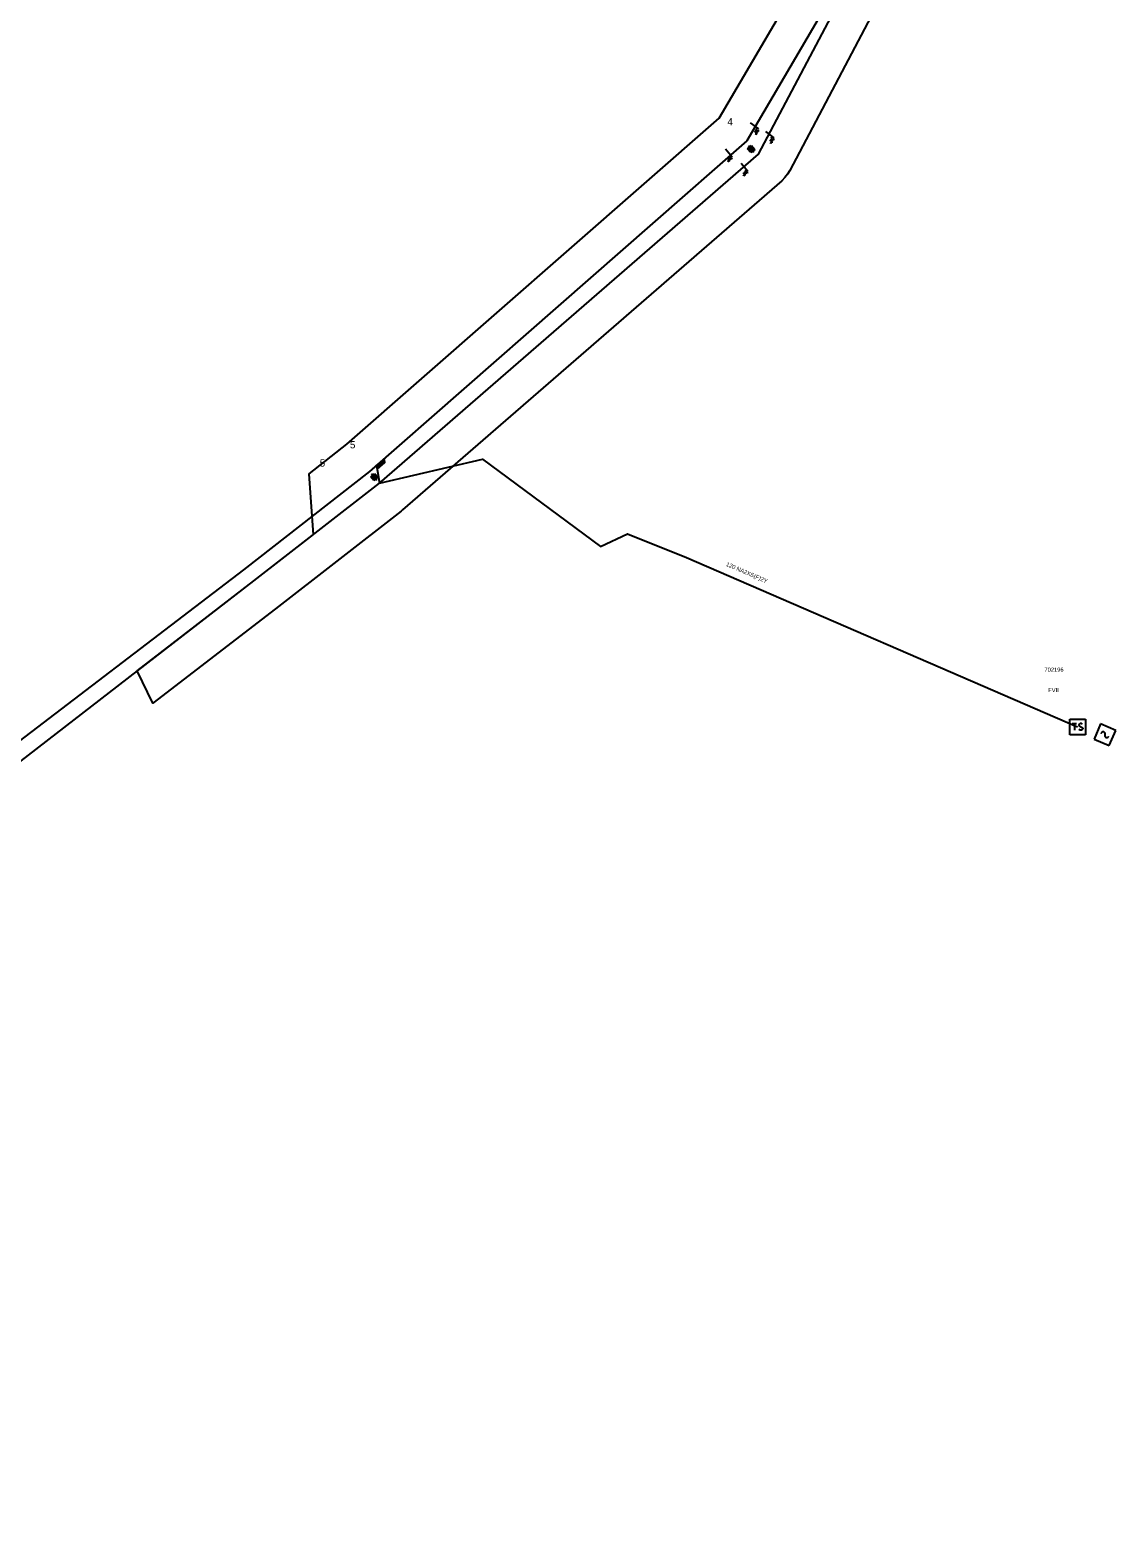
# Model space of a CAD drawing. Extents: x -788491 to -785797, y -1154753 to -1152002.
# Drawn here: x -787842.2 to -787580.7, y -1154362.4 to -1153999.5 of the extents above; entities that cross this region are included whole.
import ezdxf

# ---------------------------------------------------------------- set-up
doc = ezdxf.new("R2010")
doc.units = 0
for name, color, linetype in [('Default', 7, 'Continuous'), ('Vrstva 1', 7, 'Continuous'), ('Vrstva 11', 7, 'Continuous'), ('Vrstva 12', 7, 'Continuous'), ('Vrstva 13', 7, 'Continuous'), ('Vrstva 14', 7, 'Continuous'), ('Vrstva 15', 7, 'Continuous'), ('Vrstva 18', 7, 'Continuous'), ('Vrstva 2', 7, 'Continuous'), ('Vrstva 25', 7, 'Continuous'), ('Vrstva 26', 7, 'Continuous'), ('Vrstva 27', 7, 'Continuous'), ('Vrstva 34', 7, 'Continuous'), ('Vrstva 35', 7, 'Continuous'), ('Vrstva 5', 7, 'Continuous'), ('Vrstva 6', 7, 'Continuous')]:
    doc.layers.add(name, color=color, linetype=linetype)

# ---------------------------------------------------------------- blocks, each defined once
blk = doc.blocks.new('VN840')
at = {"layer": 'Vrstva 15'}
for points in [[(-0.01, 1.41), (-0.01, -1.09)], [(-1.51, -1.24), (-1.51, -1.15)], [(-1.48, -1.35), (-1.51, -1.24)], [(-1.33, -1.42), (-1.48, -1.35)], [(-1.27, -1.42), (-1.33, -1.42)], [(-1.13, -1.35), (-1.27, -1.42)], [(-1.09, -1.24), (-1.13, -1.35)], [(-1.09, -0.59), (-1.09, -1.24)], [(-0.68, -0.59), (-0.68, -1.42)], [(-0.68, -1.11), (-0.27, -0.59)], [(-0.54, -0.94), (-0.2, -1.42)]]:
    blk.add_lwpolyline(points, dxfattribs=at)
blk = doc.blocks.new('VN740')
at = {"layer": 'Vrstva 1'}
for points in [[(2, 2), (-2, 2)], [(-2, 2), (-2, -2)], [(0, 0), (0, 0.05), (-0.01, 0.1), (-0.02, 0.15), (-0.04, 0.2), (-0.06, 0.24), (-0.09, 0.29), (-0.12, 0.33), (-0.16, 0.36), (-0.2, 0.4), (-0.24, 0.42), (-0.29, 0.45), (-0.34, 0.47), (-0.38, 0.48), (-0.44, 0.49), (-0.49, 0.49), (-0.54, 0.49), (-0.59, 0.48), (-0.64, 0.47), (-0.69, 0.45), (-0.73, 0.43), (-0.77, 0.4), (-0.81, 0.37), (-0.85, 0.33), (-0.88, 0.29), (-0.91, 0.25), (-0.93, 0.2), (-0.95, 0.16), (-0.97, 0.11), (-0.97, 0.06), (-0.98, 0), (-0.98, 0)], [(2, -2), (2, 2)], [(-2, -2), (2, -2)], [(0, 0), (0, -0.05), (0.01, -0.1), (0.02, -0.15), (0.04, -0.2), (0.06, -0.24), (0.09, -0.28), (0.12, -0.32), (0.15, -0.36), (0.19, -0.39), (0.23, -0.42), (0.28, -0.44), (0.32, -0.46), (0.37, -0.48), (0.42, -0.49), (0.47, -0.49), (0.52, -0.49), (0.57, -0.48), (0.62, -0.47), (0.67, -0.45), (0.71, -0.43), (0.75, -0.4), (0.79, -0.37), (0.83, -0.34), (0.86, -0.3), (0.89, -0.26), (0.91, -0.21), (0.93, -0.17), (0.95, -0.12), (0.96, -0.07), (0.96, -0.02), (0.96, -0.02)]]:
    blk.add_lwpolyline(points, dxfattribs=at)
blk = doc.blocks.new('VN640')
at = {"layer": 'Vrstva 6'}
for points in [[(-1.89, 1.89), (1.89, 1.89)], [(-1.89, -1.89), (-1.89, 1.89)], [(-1.26, 0.79), (-0.22, 0.79)], [(-0.73, 0.79), (-0.73, -0.79)], [(1.2, 0.66), (0.94, 0.79), (0.66, 0.79), (0.41, 0.66), (0.28, 0.47), (0.28, 0.41), (0.41, 0.22), (1.13, -0.16), (1.26, -0.32), (1.26, -0.47), (1.13, -0.66), (0.91, -0.79), (0.63, -0.79), (0.5, -0.73), (0.28, -0.6)], [(1.89, 1.89), (1.89, -1.89)], [(1.89, -1.89), (-1.89, -1.89)]]:
    blk.add_lwpolyline(points, dxfattribs=at)
blk = doc.blocks.new('VN001')
at = {"layer": 'Default'}
for p, q in [((2.07, 3.63), (4.49, 3.63)), ((2.1, 3.68), (4.52, 3.68)), ((2.13, 3.73), (2.54, 3.73)), ((1.73, 3.03), (4.14, 3.03)), ((1.76, 3.08), (4.17, 3.08)), ((1.79, 3.13), (4.2, 3.13)), ((1.82, 3.18), (4.23, 3.18)), ((1.85, 3.23), (4.26, 3.23)), ((1.87, 3.28), (4.29, 3.28)), ((1.9, 3.33), (4.32, 3.33)), ((1.93, 3.38), (4.35, 3.38)), ((1.96, 3.43), (4.37, 3.43)), ((1.99, 3.48), (4.4, 3.48)), ((2.02, 3.53), (4.43, 3.53)), ((2.05, 3.58), (4.46, 3.58))]:
    blk.add_line(p, q, dxfattribs=at)
blk.add_lwpolyline([(2.13, 3.73), (0, 0)], dxfattribs=at)
blk.add_lwpolyline([(4.55, 3.73), (2.13, 3.73), (1.7, 2.98), (4.12, 2.99)], close=True, dxfattribs=at)
blk = doc.blocks.new('VN470')
at = {"layer": 'Vrstva 2'}
for points in [[(-1.23, 1.22), (1.23, 1.22)], [(-1.23, -1.23), (-1.23, 1.22)], [(-0.92, 0.9), (0.92, 0.9)], [(-0.92, -0.95), (-0.92, 0.9)], [(-0.61, 0.61), (0.61, 0.61)], [(-0.61, -0.62), (-0.61, 0.61)], [(-0.31, -0.27), (-0.31, 0.34)], [(-0.31, 0.34), (0.31, 0.34)], [(0, 1.22), (0, 1.97)], [(0.31, 0.34), (0.31, -0.27)], [(0.61, 0.61), (0.61, -0.62)], [(0.92, 0.9), (0.92, -0.95)], [(1.23, 1.22), (1.23, -1.23)], [(1.23, -1.23), (-1.23, -1.23)], [(0.92, -0.95), (-0.92, -0.95)], [(0.61, -0.62), (-0.61, -0.62)], [(0.31, -0.27), (-0.31, -0.27)], [(0, -1.23), (0, -1.98)]]:
    blk.add_lwpolyline(points, dxfattribs=at)

msp = doc.modelspace()

# ---------------------------------------------------------------- linework, layer by layer
at = {"layer": 'Vrstva 1'}
for points in [[(-787758.04, -1154108.54), (-787666.77, -1154029.34), (-787645.62, -1153989.29), (-787637.12, -1153973.58), (-787604.57, -1153915.79), (-787595.6, -1153858.98)], [(-787607.03, -1153915.49), (-787637.43, -1153970.03), (-787646.17, -1153986.09), (-787669.6, -1154026.19), (-787760.49, -1154105.76), (-787790.77, -1154129.38), (-787853.74, -1154177.36), (-787944.45, -1154251.81), (-787941.69, -1154348.3), (-787939.33, -1154432.99), (-788019.18, -1154537.71), (-788103.24, -1154647.83), (-788109.69, -1154656.37)], [(-787851.17, -1154180.56), (-787788.31, -1154132.05), (-787758.04, -1154108.54)]]:
    msp.add_lwpolyline(points, dxfattribs=at)
at = {"layer": 'Vrstva 35'}
msp.add_lwpolyline([(-787629.68, -1153977.68), (-787638.12, -1153993.3), (-787659.25, -1154033.31), (-787659.8, -1154034.2), (-787660.45, -1154035.02), (-787661.2, -1154035.76), (-787752.52, -1154115), (-787752.82, -1154115.25), (-787783.11, -1154138.77), (-787812.59, -1154161.52), (-787816.41, -1154153.73), (-787788.31, -1154132.06), (-787773.97, -1154120.91), (-787774.28, -1154116.51), (-787774.99, -1154106.28), (-787765.91, -1154099.2), (-787676.24, -1154020.71), (-787653.58, -1153981.92), (-787644.88, -1153965.93), (-787626.97, -1153933.8), (-787617.24, -1153933.8), (-787614.72, -1153933.8), (-787604.96, -1153933.8)], close=True, dxfattribs=at)
at = {"layer": 'Vrstva 5'}
msp.add_lwpolyline([(-787758.04, -1154108.54), (-787733.25, -1154102.75), (-787704.82, -1154123.79), (-787698.37, -1154120.76), (-787684.16, -1154126.45), (-787589.97, -1154167.21)], dxfattribs=at)

# ---------------------------------------------------------------- block references
at = {"layer": 'Vrstva 11', "rotation": 39.89939446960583}
msp.add_blockref('VN001', (-787758.04, -1154108.54), dxfattribs=at)
at = {"layer": 'Vrstva 13', "xscale": 0.49999999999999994, "yscale": 0.5000000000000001, "rotation": 39.89939446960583}
for p in [(-787668.55, -1154028.13), (-787759.31, -1154107.06)]:
    msp.add_blockref('VN470', p, dxfattribs=at)
at = {"layer": 'Vrstva 18'}
for p, rotation in [((-787667.63, -1154022.64), 53.39811110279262), ((-787663.99, -1154024.74), 53.39855277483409), ((-787673.82, -1154029.17), 39.89939446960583), ((-787670.04, -1154032.59), 39.89459998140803)]:
    msp.add_blockref('VN840', p, dxfattribs=dict(at, rotation=rotation))
at = {"layer": 'Vrstva 25', "rotation": -0.028219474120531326}
msp.add_blockref('VN640', (-787589.97, -1154167.21), dxfattribs=at)
at = {"layer": 'Vrstva 34', "rotation": -23.4002472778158}
msp.add_blockref('VN740', (-787583.37, -1154169.09), dxfattribs=at)

# ---------------------------------------------------------------- texts
at = {"layer": 'Vrstva 12'}
msp.add_text('5', height=1.75, dxfattribs=at).set_placement((-787772.43, -1154104.57))
at = {"layer": 'Vrstva 14'}
for s, p in [('4', (-787674.27, -1154022.42)), ('5', (-787765.16, -1154100.18))]:
    msp.add_text(s, height=1.75, dxfattribs=at).set_placement(p)
at = {"layer": 'Vrstva 26'}
msp.add_text('702196', height=1, dxfattribs=at).set_placement((-787597.94, -1154153.94))
at = {"layer": 'Vrstva 27'}
msp.add_text('FVE', height=1, dxfattribs=at).set_placement((-787597.03, -1154158.85))
at = {"layer": 'Vrstva 6'}
msp.add_text('120 NA2XS(F)2Y', height=1, rotation=336.6, dxfattribs=at).set_placement((-787674.69, -1154128.42))

doc.saveas('drawing.dxf')
